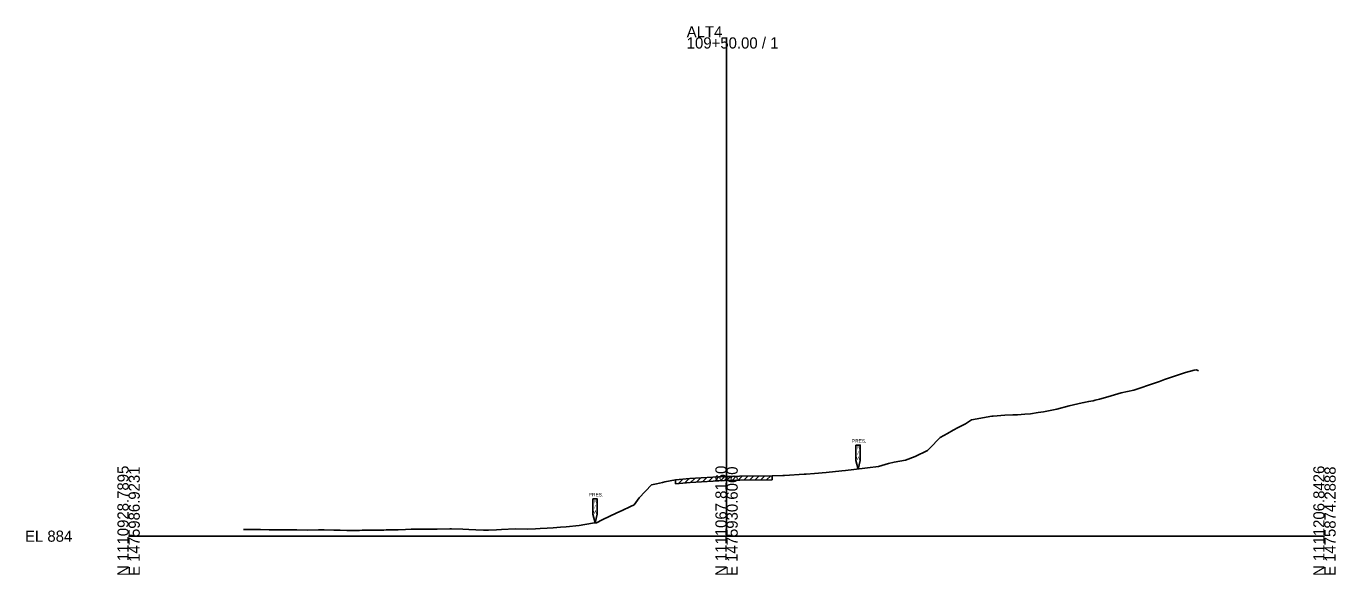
# Model space of a CAD drawing. Extents: x -26 to 1303, y -10 to 19562.
# Drawn here: x 974.3 to 1302.8, y 5990.3 to 6128 of the extents above; entities that cross this region are included whole.
import ezdxf

# ---------------------------------------------------------------- set-up
doc = ezdxf.new("R2010")
doc.units = 0
for name, color, linetype in [('RD_GPK_XS_Cell', 7, 'Continuous'), ('RD_XS_ExGround', 7, 'Continuous'), ('RD_XS_ExPaveRet', 7, 'Continuous'), ('RD_XS_ExRW', 7, 'Continuous'), ('RD_XS_TX_Elev_EX', 7, 'Continuous')]:
    doc.layers.add(name, color=color, linetype=linetype)

msp = doc.modelspace()

# ---------------------------------------------------------------- linework, layer by layer
at = {"layer": 'RD_GPK_XS_Cell'}
for p, q in [((1150, 6000), (1150, 6125.15)), ((1000, 6000), (1150, 6000)), ((1150, 6000), (1300, 6000))]:
    msp.add_line(p, q, dxfattribs=at)
at = {"layer": 'RD_XS_ExGround'}
msp.add_lwpolyline([(1028.86, 6001.65), (1029.54, 6001.68), (1030.05, 6001.65), (1032.06, 6001.64), (1033.09, 6001.64), (1035.29, 6001.6), (1036.79, 6001.6), (1038.53, 6001.58), (1041.08, 6001.59), (1041.77, 6001.59), (1042.23, 6001.58), (1045, 6001.55), (1047.67, 6001.57), (1048.24, 6001.57), (1049.07, 6001.57), (1051.48, 6001.54), (1053.09, 6001.49), (1054.71, 6001.44), (1057.06, 6001.45), (1057.95, 6001.46), (1058.56, 6001.48), (1061.19, 6001.54), (1064, 6001.55), (1064.6, 6001.56), (1065.05, 6001.57), (1066.91, 6001.61), (1067.66, 6001.61), (1069.44, 6001.67), (1070.9, 6001.72), (1073.04, 6001.73), (1074.13, 6001.73), (1074.88, 6001.75), (1077.37, 6001.79), (1080.61, 6001.84), (1081.03, 6001.83), (1083.84, 6001.76), (1085.34, 6001.7), (1087.08, 6001.58), (1089.02, 6001.51), (1090.32, 6001.49), (1092.25, 6001.58), (1093.55, 6001.67), (1097.01, 6001.82), (1100.03, 6001.8), (1102.08, 6001.85), (1103.26, 6001.89), (1105, 6002), (1106.5, 6002.11), (1108.37, 6002.27), (1109.74, 6002.36), (1113, 6002.68), (1116.34, 6003.23), (1117.39, 6003.37), (1118.82, 6004.11), (1122.49, 6005.83), (1123.84, 6006.47), (1125.92, 6007.44), (1126.8, 6007.85), (1128.12, 6009.62), (1131.19, 6012.89), (1132.42, 6013.15), (1133.93, 6013.49), (1134.49, 6013.6), (1137.23, 6014.17), (1140.8, 6014.43), (1149.42, 6014.98), (1150, 6014.99), (1153.29, 6015.03), (1161.41, 6015.16), (1164.11, 6015.22), (1164.54, 6015.24), (1169.47, 6015.55), (1169.94, 6015.57), (1172.08, 6015.76), (1174.99, 6015.95), (1178.93, 6016.36), (1179.83, 6016.47), (1181.93, 6016.7), (1185.4, 6017.11), (1188.14, 6017.51), (1190.66, 6018.26), (1192.02, 6018.56), (1194.93, 6019.06), (1197.31, 6019.96), (1200.37, 6021.47), (1200.89, 6022.02), (1203.61, 6024.74), (1205.46, 6025.75), (1206.84, 6026.58), (1208.13, 6027.25), (1209.98, 6028.17), (1211.48, 6029.21), (1216.55, 6030.09), (1216.87, 6030.11), (1219.79, 6030.33), (1221.78, 6030.41), (1223.03, 6030.44), (1224.86, 6030.61), (1226.26, 6030.7), (1228.16, 6031), (1229.5, 6031.19), (1232.85, 6031.85), (1235.97, 6032.73), (1238.1, 6033.18), (1239.21, 6033.42), (1239.68, 6033.55), (1240.84, 6033.76), (1241.98, 6033.98), (1242.45, 6034.09), (1243.54, 6034.37), (1245.68, 6034.95), (1248.98, 6035.94), (1252.16, 6036.64), (1254.42, 6037.4), (1255.39, 6037.73), (1256.82, 6038.2), (1258.63, 6038.85), (1259.86, 6039.28), (1261.87, 6039.99), (1265.1, 6041.03), (1267.32, 6041.63), (1267.92, 6041.72), (1268.41, 6041.47)], dxfattribs=at)
at = {"layer": 'RD_XS_ExPaveRet'}
for p, q in [((1137.23, 6013.94), (1137.48, 6014.19)), ((1137.23, 6014.17), (1137.23, 6013.17)), ((1137.93, 6013.22), (1139, 6014.3)), ((1139.45, 6013.34), (1140.53, 6014.41)), ((1140.98, 6013.45), (1142.04, 6014.51)), ((1142.49, 6013.54), (1143.55, 6014.61)), ((1144, 6013.64), (1145.06, 6014.7)), ((1145.51, 6013.74), (1146.58, 6014.8)), ((1147.02, 6013.83), (1148.09, 6014.9)), ((1148.53, 6013.93), (1149.59, 6014.98)), ((1150.01, 6013.99), (1151.02, 6015)), ((1151.44, 6014.01), (1152.45, 6015.02)), ((1152.88, 6014.03), (1153.89, 6015.04)), ((1154.31, 6014.05), (1155.32, 6015.06)), ((1155.75, 6014.08), (1156.76, 6015.09)), ((1157.19, 6014.1), (1158.2, 6015.11)), ((1158.62, 6014.12), (1159.64, 6015.13)), ((1160.06, 6014.14), (1161.07, 6015.16)), ((1161.41, 6015.16), (1161.41, 6014.16))]:
    msp.add_line(p, q, dxfattribs=at)
msp.add_lwpolyline([(1137.23, 6013.17), (1140.87, 6013.44), (1149.46, 6013.99), (1153.31, 6014.04), (1161.41, 6014.17)], dxfattribs=at)
at = {"layer": 'RD_XS_ExRW'}
for points in [[(1182.45, 6022.84), (1183.55, 6022.84), (1183.55, 6019.01), (1183, 6016.82), (1182.45, 6019.01)], [(1116.45, 6009.33), (1117.55, 6009.33), (1117.55, 6005.5), (1117, 6003.32), (1116.45, 6005.5)]]:
    msp.add_lwpolyline(points, close=True, dxfattribs=at)

# ---------------------------------------------------------------- texts
at = {"layer": 'RD_GPK_XS_Cell'}
for s, p in [('ALT4', (1140, 6125.15)), ('109+50.00 / 1', (1140, 6122.35)), ('EL 884', (974, 5998.6))]:
    msp.add_text(s, height=2.8, dxfattribs=at).set_placement(p)
for s, p in [('N 1110928.7895', (1000, 5990)), ('E 1475986.9231', (1002.8, 5990)), ('N 1111067.8160', (1150, 5990)), ('E 1475930.6060', (1152.8, 5990)), ('N 1111206.8426', (1300, 5990)), ('E 1475874.2888', (1302.8, 5990))]:
    msp.add_text(s, height=2.8, rotation=90, dxfattribs=at).set_placement(p)
at = {"layer": 'RD_XS_ExRW'}
for s, p in [('PRES.', (1181.45, 6023.47)), ('R', (1182.71, 6021.75)), ('W', (1182.53, 6019.12)), ('/', (1182.83, 6020.44)), ('PRES.', (1115.45, 6009.96)), ('R', (1116.71, 6008.24)), ('W', (1116.53, 6005.62)), ('/', (1116.83, 6006.93))]:
    msp.add_text(s, height=0.875, dxfattribs=at).set_placement(p)
at = {"layer": 'RD_XS_TX_Elev_EX'}
msp.add_text('898.99', height=0.5, dxfattribs=at).set_placement((1148.98, 6014.49))

doc.saveas('drawing.dxf')
